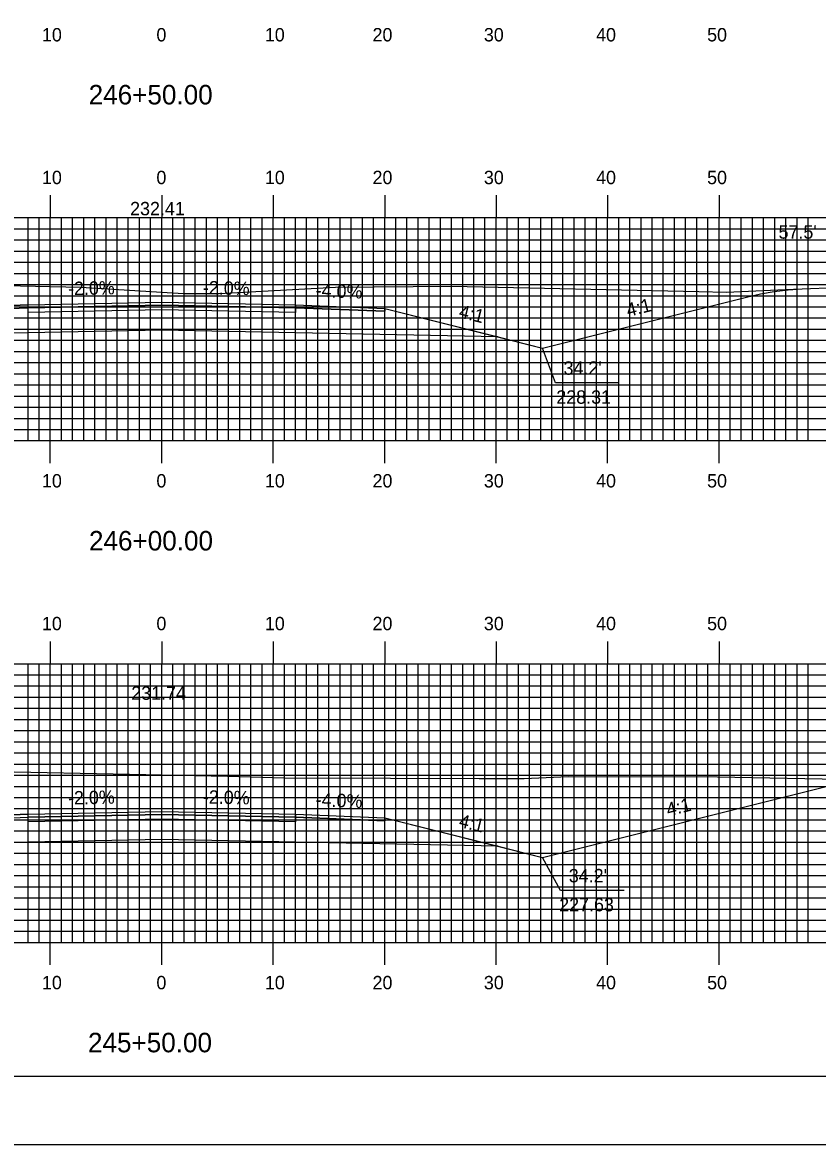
# Model space of a CAD drawing. Extents: x 1803110 to 1803453, y 442591 to 442811.
# Drawn here: x 1803263.1 to 1803334.5, y 442590.5 to 442691.2 of the extents above; entities that cross this region are included whole.
import ezdxf

# ---------------------------------------------------------------- set-up
doc = ezdxf.new("R2010")
doc.units = 0
for name, color, linetype in [('ANNOTATION', 7, 'Continuous'), ('BORDER', 7, 'Continuous'), ('D_Roadway_Centerline', 7, 'Continuous'), ('D_Roadway_Centerline_Text', 7, 'Continuous'), ('D_Roadway_Edge_Shoulder', 7, 'Continuous'), ('D_Roadway_Edge_TW', 7, 'Continuous'), ('D_Roadway_Pavement', 7, 'Continuous'), ('D_Roadway_SlopeLines', 7, 'Continuous'), ('D_Roadway_SubGrade', 7, 'Continuous'), ('D_Text_Standard', 7, 'Continuous'), ('H_V ANNOTATION', 7, 'Continuous'), ('MAJOR', 7, 'Continuous'), ('MINOR', 7, 'Continuous'), ('PLOT BOUNDARY', 7, 'Continuous'), ('S_Roadway_Centerline', 7, 'Continuous')]:
    doc.layers.add(name, color=color, linetype=linetype)

msp = doc.modelspace()

# ---------------------------------------------------------------- linework, layer by layer
at = {"layer": 'ANNOTATION'}
for points in [[(1803316.64, 442658.85), (1803310.95, 442658.85), (1803309.8, 442661.97)], [(1803317.11, 442613.34), (1803311.42, 442613.34), (1803309.8, 442616.3)]]:
    msp.add_lwpolyline(points, dxfattribs=at)
at = {"layer": 'BORDER'}
msp.add_lwpolyline([(1803126.03, 442596.67), (1803446.03, 442596.67), (1803446.03, 442806.67), (1803126.03, 442806.67)], close=True, dxfattribs=at)
at = {"layer": 'D_Roadway_Centerline'}
for points in [[(1803216.26, 442667.67), (1803217.51, 442667.62), (1803218.76, 442667.5), (1803220.01, 442667.3), (1803221.26, 442667.02), (1803241.45, 442661.97), (1803245.45, 442662.97), (1803255.63, 442665.52), (1803263.63, 442665.84), (1803275.63, 442666.08), (1803287.63, 442665.84), (1803295.63, 442665.52), (1803305.8, 442662.97), (1803309.8, 442661.97), (1803328.09, 442666.55), (1803329.34, 442666.83), (1803330.59, 442667.04), (1803331.84, 442667.19), (1803333.09, 442667.27)], [(1803208.67, 442623.85), (1803209.92, 442623.82), (1803211.17, 442623.71), (1803212.42, 442623.52), (1803213.67, 442623.24), (1803241.45, 442616.3), (1803245.45, 442617.3), (1803255.63, 442619.84), (1803263.63, 442620.16), (1803275.63, 442620.4), (1803287.63, 442620.16), (1803295.63, 442619.84), (1803305.8, 442617.3), (1803309.8, 442616.3), (1803335.24, 442622.66), (1803336.49, 442622.93), (1803337.74, 442623.13), (1803338.99, 442623.24), (1803340.24, 442623.28)]]:
    msp.add_lwpolyline(points, dxfattribs=at)
at = {"layer": 'D_Roadway_Edge_Shoulder'}
for points in [[(1803263.63, 442665.84), (1803255.63, 442665.52), (1803255.63, 442665.27), (1803263.63, 442665.59)], [(1803287.63, 442665.84), (1803295.63, 442665.52), (1803295.63, 442665.27), (1803287.63, 442665.59)], [(1803263.63, 442620.16), (1803255.63, 442619.84), (1803255.63, 442619.59), (1803263.63, 442619.91)], [(1803287.63, 442620.16), (1803295.63, 442619.84), (1803295.63, 442619.59), (1803287.63, 442619.91)]]:
    msp.add_lwpolyline(points, close=True, dxfattribs=at)
at = {"layer": 'D_Roadway_Edge_TW'}
for points in [[(1803263.63, 442665.59), (1803263.63, 442665.84), (1803275.63, 442666.08), (1803287.63, 442665.84), (1803287.63, 442665.59), (1803275.63, 442665.83)], [(1803263.63, 442619.91), (1803263.63, 442620.16), (1803275.63, 442620.4), (1803287.63, 442620.16), (1803287.63, 442619.91), (1803275.63, 442620.15)]]:
    msp.add_lwpolyline(points, close=True, dxfattribs=at)
at = {"layer": 'D_Roadway_Pavement'}
for points in [[(1803263.63, 442665.17), (1803263.63, 442665.59), (1803275.63, 442665.83), (1803287.63, 442665.59), (1803287.63, 442665.17), (1803275.63, 442665.41)], [(1803263.63, 442619.49), (1803263.63, 442619.91), (1803275.63, 442620.15), (1803287.63, 442619.91), (1803287.63, 442619.49), (1803275.63, 442619.73)]]:
    msp.add_lwpolyline(points, close=True, dxfattribs=at)
at = {"layer": 'D_Roadway_SlopeLines'}
for points in [[(1803309.8, 442661.97), (1803328.09, 442666.55), (1803329.34, 442666.83), (1803330.59, 442667.04), (1803331.84, 442667.19), (1803333.09, 442667.27)], [(1803295.63, 442665.52), (1803309.8, 442661.97)], [(1803309.8, 442616.3), (1803335.24, 442622.66), (1803336.49, 442622.93), (1803337.74, 442623.13), (1803338.99, 442623.24), (1803340.24, 442623.28)], [(1803295.63, 442619.84), (1803309.8, 442616.3)]]:
    msp.add_lwpolyline(points, dxfattribs=at)
at = {"layer": 'D_Roadway_SubGrade'}
for points in [[(1803263.63, 442663.34), (1803245.45, 442662.97), (1803255.63, 442665.52), (1803255.63, 442665.27), (1803263.63, 442665.59), (1803275.63, 442665.83), (1803287.63, 442665.59), (1803295.63, 442665.27), (1803295.63, 442665.52), (1803305.8, 442662.97), (1803287.63, 442663.34), (1803275.63, 442663.58)], [(1803263.63, 442617.66), (1803245.45, 442617.3), (1803255.63, 442619.84), (1803255.63, 442619.59), (1803263.63, 442619.91), (1803275.63, 442620.15), (1803287.63, 442619.91), (1803295.63, 442619.59), (1803295.63, 442619.84), (1803305.8, 442617.3), (1803287.63, 442617.66), (1803275.63, 442617.9)]]:
    msp.add_lwpolyline(points, close=True, dxfattribs=at)
at = {"layer": 'MAJOR'}
for p, q in [((1803265.63, 442675.67), (1803265.63, 442673.67)), ((1803275.63, 442675.67), (1803275.63, 442673.67)), ((1803285.63, 442675.67), (1803285.63, 442673.67)), ((1803295.63, 442675.67), (1803295.63, 442673.67)), ((1803305.63, 442675.67), (1803305.63, 442673.67)), ((1803315.63, 442675.67), (1803315.63, 442673.67)), ((1803325.63, 442675.67), (1803325.63, 442673.67)), ((1803135.63, 442673.67), (1803415.63, 442673.67)), ((1803135.63, 442673.67), (1803415.63, 442673.67)), ((1803265.63, 442653.67), (1803265.63, 442673.67)), ((1803275.63, 442653.67), (1803275.63, 442673.67)), ((1803285.63, 442653.67), (1803285.63, 442673.67)), ((1803295.63, 442653.67), (1803295.63, 442673.67)), ((1803305.63, 442653.67), (1803305.63, 442673.67)), ((1803315.63, 442653.67), (1803315.63, 442673.67)), ((1803325.63, 442653.67), (1803325.63, 442673.67)), ((1803135.63, 442668.67), (1803415.63, 442668.67)), ((1803135.63, 442663.67), (1803415.63, 442663.67)), ((1803135.63, 442658.67), (1803415.63, 442658.67)), ((1803135.63, 442653.67), (1803415.63, 442653.67)), ((1803135.63, 442653.67), (1803415.63, 442653.67)), ((1803265.63, 442651.66), (1803265.63, 442653.67)), ((1803275.63, 442651.66), (1803275.63, 442653.67)), ((1803285.63, 442651.66), (1803285.63, 442653.67)), ((1803295.63, 442651.66), (1803295.63, 442653.67)), ((1803305.63, 442651.66), (1803305.63, 442653.67)), ((1803315.63, 442651.66), (1803315.63, 442653.67)), ((1803325.63, 442651.66), (1803325.63, 442653.67)), ((1803265.63, 442635.67), (1803265.63, 442633.67)), ((1803275.63, 442635.67), (1803275.63, 442633.67)), ((1803285.63, 442635.67), (1803285.63, 442633.67)), ((1803295.63, 442635.67), (1803295.63, 442633.67)), ((1803305.63, 442635.67), (1803305.63, 442633.67)), ((1803315.63, 442635.67), (1803315.63, 442633.67)), ((1803325.63, 442635.67), (1803325.63, 442633.67)), ((1803135.63, 442633.67), (1803415.63, 442633.67)), ((1803135.63, 442633.67), (1803415.63, 442633.67)), ((1803265.63, 442608.67), (1803265.63, 442633.67)), ((1803275.63, 442608.67), (1803275.63, 442633.67)), ((1803285.63, 442608.67), (1803285.63, 442633.67)), ((1803295.63, 442608.67), (1803295.63, 442633.67)), ((1803305.63, 442608.67), (1803305.63, 442633.67)), ((1803315.63, 442608.67), (1803315.63, 442633.67)), ((1803325.63, 442608.67), (1803325.63, 442633.67)), ((1803135.63, 442628.67), (1803415.63, 442628.67)), ((1803135.63, 442623.67), (1803415.63, 442623.67)), ((1803135.63, 442618.67), (1803415.63, 442618.67)), ((1803135.63, 442613.67), (1803415.63, 442613.67)), ((1803135.63, 442608.67), (1803415.63, 442608.67)), ((1803135.63, 442608.67), (1803415.63, 442608.67)), ((1803265.63, 442606.66), (1803265.63, 442608.67)), ((1803275.63, 442606.66), (1803275.63, 442608.67)), ((1803285.63, 442606.66), (1803285.63, 442608.67)), ((1803295.63, 442606.66), (1803295.63, 442608.67)), ((1803305.63, 442606.66), (1803305.63, 442608.67)), ((1803315.63, 442606.66), (1803315.63, 442608.67)), ((1803325.63, 442606.66), (1803325.63, 442608.67))]:
    msp.add_line(p, q, dxfattribs=at)
at = {"layer": 'MINOR'}
for p, q in [((1803263.63, 442653.67), (1803263.63, 442673.67)), ((1803264.63, 442653.67), (1803264.63, 442673.67)), ((1803266.63, 442653.67), (1803266.63, 442673.67)), ((1803267.63, 442653.67), (1803267.63, 442673.67)), ((1803268.63, 442653.67), (1803268.63, 442673.67)), ((1803269.63, 442653.67), (1803269.63, 442673.67)), ((1803270.63, 442653.67), (1803270.63, 442673.67)), ((1803271.63, 442653.67), (1803271.63, 442673.67)), ((1803272.63, 442653.67), (1803272.63, 442673.67)), ((1803273.63, 442653.67), (1803273.63, 442673.67)), ((1803274.63, 442653.67), (1803274.63, 442673.67)), ((1803276.63, 442653.67), (1803276.63, 442673.67)), ((1803277.63, 442653.67), (1803277.63, 442673.67)), ((1803278.63, 442653.67), (1803278.63, 442673.67)), ((1803279.63, 442653.67), (1803279.63, 442673.67)), ((1803280.63, 442653.67), (1803280.63, 442673.67)), ((1803281.63, 442653.67), (1803281.63, 442673.67)), ((1803282.63, 442653.67), (1803282.63, 442673.67)), ((1803283.63, 442653.67), (1803283.63, 442673.67)), ((1803284.63, 442653.67), (1803284.63, 442673.67)), ((1803286.63, 442653.67), (1803286.63, 442673.67)), ((1803287.63, 442653.67), (1803287.63, 442673.67)), ((1803288.63, 442653.67), (1803288.63, 442673.67)), ((1803289.63, 442653.67), (1803289.63, 442673.67)), ((1803290.63, 442653.67), (1803290.63, 442673.67)), ((1803291.63, 442653.67), (1803291.63, 442673.67)), ((1803292.63, 442653.67), (1803292.63, 442673.67)), ((1803293.63, 442653.67), (1803293.63, 442673.67)), ((1803294.63, 442653.67), (1803294.63, 442673.67)), ((1803296.63, 442653.67), (1803296.63, 442673.67)), ((1803297.63, 442653.67), (1803297.63, 442673.67)), ((1803298.63, 442653.67), (1803298.63, 442673.67)), ((1803299.63, 442653.67), (1803299.63, 442673.67)), ((1803300.63, 442653.67), (1803300.63, 442673.67)), ((1803301.63, 442653.67), (1803301.63, 442673.67)), ((1803302.63, 442653.67), (1803302.63, 442673.67)), ((1803303.63, 442653.67), (1803303.63, 442673.67)), ((1803304.63, 442653.67), (1803304.63, 442673.67)), ((1803306.63, 442653.67), (1803306.63, 442673.67)), ((1803307.63, 442653.67), (1803307.63, 442673.67)), ((1803308.63, 442653.67), (1803308.63, 442673.67)), ((1803309.63, 442653.67), (1803309.63, 442673.67)), ((1803310.63, 442653.67), (1803310.63, 442673.67)), ((1803311.63, 442653.67), (1803311.63, 442673.67)), ((1803312.63, 442653.67), (1803312.63, 442673.67)), ((1803313.63, 442653.67), (1803313.63, 442673.67)), ((1803314.63, 442653.67), (1803314.63, 442673.67)), ((1803316.63, 442653.67), (1803316.63, 442673.67)), ((1803317.63, 442653.67), (1803317.63, 442673.67)), ((1803318.63, 442653.67), (1803318.63, 442673.67)), ((1803319.63, 442653.67), (1803319.63, 442673.67)), ((1803320.63, 442653.67), (1803320.63, 442673.67)), ((1803321.63, 442653.67), (1803321.63, 442673.67)), ((1803322.63, 442653.67), (1803322.63, 442673.67)), ((1803323.63, 442653.67), (1803323.63, 442673.67)), ((1803324.63, 442653.67), (1803324.63, 442673.67)), ((1803326.63, 442653.67), (1803326.63, 442673.67)), ((1803327.63, 442653.67), (1803327.63, 442673.67)), ((1803328.63, 442653.67), (1803328.63, 442673.67)), ((1803329.63, 442653.67), (1803329.63, 442673.67)), ((1803330.63, 442653.67), (1803330.63, 442673.67)), ((1803331.63, 442653.67), (1803331.63, 442673.67)), ((1803332.63, 442653.67), (1803332.63, 442673.67)), ((1803333.63, 442653.67), (1803333.63, 442673.67)), ((1803135.63, 442672.67), (1803415.63, 442672.67)), ((1803135.63, 442671.67), (1803415.63, 442671.67)), ((1803135.63, 442670.67), (1803415.63, 442670.67)), ((1803135.63, 442669.67), (1803415.63, 442669.67)), ((1803135.63, 442667.67), (1803415.63, 442667.67)), ((1803135.63, 442666.67), (1803415.63, 442666.67)), ((1803135.63, 442665.67), (1803415.63, 442665.67)), ((1803135.63, 442664.67), (1803415.63, 442664.67)), ((1803135.63, 442662.67), (1803415.63, 442662.67)), ((1803135.63, 442661.67), (1803415.63, 442661.67)), ((1803135.63, 442660.67), (1803415.63, 442660.67)), ((1803135.63, 442659.67), (1803415.63, 442659.67)), ((1803135.63, 442657.67), (1803415.63, 442657.67)), ((1803135.63, 442656.67), (1803415.63, 442656.67)), ((1803135.63, 442655.67), (1803415.63, 442655.67)), ((1803135.63, 442654.67), (1803415.63, 442654.67)), ((1803263.63, 442608.67), (1803263.63, 442633.67)), ((1803264.63, 442608.67), (1803264.63, 442633.67)), ((1803266.63, 442608.67), (1803266.63, 442633.67)), ((1803267.63, 442608.67), (1803267.63, 442633.67)), ((1803268.63, 442608.67), (1803268.63, 442633.67)), ((1803269.63, 442608.67), (1803269.63, 442633.67)), ((1803270.63, 442608.67), (1803270.63, 442633.67)), ((1803271.63, 442608.67), (1803271.63, 442633.67)), ((1803272.63, 442608.67), (1803272.63, 442633.67)), ((1803273.63, 442608.67), (1803273.63, 442633.67)), ((1803274.63, 442608.67), (1803274.63, 442633.67)), ((1803276.63, 442608.67), (1803276.63, 442633.67)), ((1803277.63, 442608.67), (1803277.63, 442633.67)), ((1803278.63, 442608.67), (1803278.63, 442633.67)), ((1803279.63, 442608.67), (1803279.63, 442633.67)), ((1803280.63, 442608.67), (1803280.63, 442633.67)), ((1803281.63, 442608.67), (1803281.63, 442633.67)), ((1803282.63, 442608.67), (1803282.63, 442633.67)), ((1803283.63, 442608.67), (1803283.63, 442633.67)), ((1803284.63, 442608.67), (1803284.63, 442633.67)), ((1803286.63, 442608.67), (1803286.63, 442633.67)), ((1803287.63, 442608.67), (1803287.63, 442633.67)), ((1803288.63, 442608.67), (1803288.63, 442633.67)), ((1803289.63, 442608.67), (1803289.63, 442633.67)), ((1803290.63, 442608.67), (1803290.63, 442633.67)), ((1803291.63, 442608.67), (1803291.63, 442633.67)), ((1803292.63, 442608.67), (1803292.63, 442633.67)), ((1803293.63, 442608.67), (1803293.63, 442633.67)), ((1803294.63, 442608.67), (1803294.63, 442633.67)), ((1803296.63, 442608.67), (1803296.63, 442633.67)), ((1803297.63, 442608.67), (1803297.63, 442633.67)), ((1803298.63, 442608.67), (1803298.63, 442633.67)), ((1803299.63, 442608.67), (1803299.63, 442633.67)), ((1803300.63, 442608.67), (1803300.63, 442633.67)), ((1803301.63, 442608.67), (1803301.63, 442633.67)), ((1803302.63, 442608.67), (1803302.63, 442633.67)), ((1803303.63, 442608.67), (1803303.63, 442633.67)), ((1803304.63, 442608.67), (1803304.63, 442633.67)), ((1803306.63, 442608.67), (1803306.63, 442633.67)), ((1803307.63, 442608.67), (1803307.63, 442633.67)), ((1803308.63, 442608.67), (1803308.63, 442633.67)), ((1803309.63, 442608.67), (1803309.63, 442633.67)), ((1803310.63, 442608.67), (1803310.63, 442633.67)), ((1803311.63, 442608.67), (1803311.63, 442633.67)), ((1803312.63, 442608.67), (1803312.63, 442633.67)), ((1803313.63, 442608.67), (1803313.63, 442633.67)), ((1803314.63, 442608.67), (1803314.63, 442633.67)), ((1803316.63, 442608.67), (1803316.63, 442633.67)), ((1803317.63, 442608.67), (1803317.63, 442633.67)), ((1803318.63, 442608.67), (1803318.63, 442633.67)), ((1803319.63, 442608.67), (1803319.63, 442633.67)), ((1803320.63, 442608.67), (1803320.63, 442633.67)), ((1803321.63, 442608.67), (1803321.63, 442633.67)), ((1803322.63, 442608.67), (1803322.63, 442633.67)), ((1803323.63, 442608.67), (1803323.63, 442633.67)), ((1803324.63, 442608.67), (1803324.63, 442633.67)), ((1803326.63, 442608.67), (1803326.63, 442633.67)), ((1803327.63, 442608.67), (1803327.63, 442633.67)), ((1803328.63, 442608.67), (1803328.63, 442633.67)), ((1803329.63, 442608.67), (1803329.63, 442633.67)), ((1803330.63, 442608.67), (1803330.63, 442633.67)), ((1803331.63, 442608.67), (1803331.63, 442633.67)), ((1803332.63, 442608.67), (1803332.63, 442633.67)), ((1803333.63, 442608.67), (1803333.63, 442633.67)), ((1803135.63, 442632.67), (1803415.63, 442632.67)), ((1803135.63, 442631.67), (1803415.63, 442631.67)), ((1803135.63, 442630.67), (1803415.63, 442630.67)), ((1803135.63, 442629.67), (1803415.63, 442629.67)), ((1803135.63, 442627.67), (1803415.63, 442627.67)), ((1803135.63, 442626.67), (1803415.63, 442626.67)), ((1803135.63, 442625.67), (1803415.63, 442625.67)), ((1803135.63, 442624.67), (1803415.63, 442624.67)), ((1803135.63, 442622.67), (1803415.63, 442622.67)), ((1803135.63, 442621.67), (1803415.63, 442621.67)), ((1803135.63, 442620.67), (1803415.63, 442620.67)), ((1803135.63, 442619.67), (1803415.63, 442619.67)), ((1803135.63, 442617.67), (1803415.63, 442617.67)), ((1803135.63, 442616.67), (1803415.63, 442616.67)), ((1803135.63, 442615.67), (1803415.63, 442615.67)), ((1803135.63, 442614.67), (1803415.63, 442614.67)), ((1803135.63, 442612.67), (1803415.63, 442612.67)), ((1803135.63, 442611.67), (1803415.63, 442611.67)), ((1803135.63, 442610.67), (1803415.63, 442610.67)), ((1803135.63, 442609.67), (1803415.63, 442609.67))]:
    msp.add_line(p, q, dxfattribs=at)
at = {"layer": 'PLOT BOUNDARY'}
msp.add_lwpolyline([(1803109.84, 442590.55), (1803449.84, 442590.55), (1803449.84, 442810.55), (1803109.84, 442810.55)], close=True, dxfattribs=at)
at = {"layer": 'S_Roadway_Centerline'}
for points in [[(1803200.7, 442667.63), (1803217.19, 442667.67), (1803220.81, 442667.62), (1803225.55, 442667.56), (1803233.02, 442667.5), (1803238.55, 442667.5), (1803251.74, 442667.64), (1803255.42, 442667.71), (1803258.86, 442667.64), (1803268.38, 442667.44), (1803277.59, 442666.86), (1803280.77, 442666.87), (1803291.21, 442667.42), (1803301.67, 442667.52), (1803323.83, 442667.05), (1803326.31, 442666.97), (1803329.6, 442667.13), (1803331.57, 442667.21), (1803337.63, 442667.46)], [(1803203.03, 442623.87), (1803209.31, 442623.84), (1803218.86, 442623.97), (1803234.63, 442623.63), (1803239.72, 442623.61), (1803260.41, 442624.01), (1803260.67, 442624), (1803260.89, 442624), (1803272.73, 442623.75), (1803281.53, 442623.59), (1803286.63, 442623.44), (1803296.14, 442623.39), (1803304.1, 442623.38), (1803308.16, 442623.38), (1803312.1, 442623.56), (1803325.5, 442623.51), (1803338.02, 442623.28)]]:
    msp.add_lwpolyline(points, dxfattribs=at)

# ---------------------------------------------------------------- texts
at = {"layer": 'ANNOTATION'}
for s, rotation, p in [('-2.0%', 1.1458, (1803267.23, 442666.71)), ('-2.0%', 358.8542, (1803279.31, 442666.8)), ('-4.0%', 357.7094, (1803289.42, 442666.57)), ('4:1', 345.9638, (1803302.22, 442664.73)), ('4:1', 14.0362, (1803317.48, 442664.76)), ('-2.0%', 1.1458, (1803267.23, 442621.03)), ('-2.0%', 358.8542, (1803279.31, 442621.13)), ('-4.0%', 357.7094, (1803289.42, 442620.89)), ('4:1', 14.0362, (1803321.06, 442619.97)), ('4:1', 345.9638, (1803302.22, 442619.05))]:
    msp.add_text(s, height=1.2, rotation=rotation, dxfattribs=at).set_placement(p)
for s, p in [("34.2'", (1803311.68, 442659.58)), ('228.31', (1803311.03, 442656.98)), ("34.2'", (1803312.15, 442614.06)), ('227.63', (1803311.29, 442611.46))]:
    msp.add_text(s, height=1.2, dxfattribs=at).set_placement(p)
at = {"layer": 'D_Roadway_Centerline'}
for s, p in [('C', (1803275.62, 442666.08)), ('L', (1803275.63, 442666.07)), ('C', (1803275.62, 442620.4)), ('L', (1803275.63, 442620.39))]:
    msp.add_text(s, height=0.0146, dxfattribs=at).set_placement(p)
at = {"layer": 'D_Roadway_Centerline_Text'}
for s, p in [('232.41', (1803272.79, 442673.88)), ('231.74', (1803272.89, 442630.43))]:
    msp.add_text(s, height=1.2, dxfattribs=at).set_placement(p)
at = {"layer": 'D_Text_Standard'}
msp.add_text("57.5'", height=1.2, dxfattribs=at).set_placement((1803330.97, 442671.78))
at = {"layer": 'H_V ANNOTATION'}
for s, height, p in [('10', 1.2, (1803264.88, 442689.47)), ('0', 1.2, (1803275.15, 442689.47)), ('10', 1.2, (1803284.88, 442689.47)), ('20', 1.2, (1803294.54, 442689.47)), ('30', 1.2, (1803304.53, 442689.47)), ('40', 1.2, (1803314.6, 442689.47)), ('50', 1.2, (1803324.56, 442689.47)), ('246+50.00', 1.75, (1803269.07, 442683.82)), ('10', 1.2, (1803264.88, 442676.67)), ('0', 1.2, (1803275.15, 442676.67)), ('10', 1.2, (1803284.88, 442676.67)), ('20', 1.2, (1803294.54, 442676.67)), ('30', 1.2, (1803304.53, 442676.67)), ('40', 1.2, (1803314.6, 442676.67)), ('50', 1.2, (1803324.56, 442676.67)), ('10', 1.2, (1803264.88, 442649.47)), ('0', 1.2, (1803275.15, 442649.47)), ('10', 1.2, (1803284.88, 442649.47)), ('20', 1.2, (1803294.54, 442649.47)), ('30', 1.2, (1803304.53, 442649.47)), ('40', 1.2, (1803314.6, 442649.47)), ('50', 1.2, (1803324.56, 442649.47)), ('246+00.00', 1.75, (1803269.1, 442643.82)), ('10', 1.2, (1803264.88, 442636.67)), ('0', 1.2, (1803275.15, 442636.67)), ('10', 1.2, (1803284.88, 442636.67)), ('20', 1.2, (1803294.54, 442636.67)), ('30', 1.2, (1803304.53, 442636.67)), ('40', 1.2, (1803314.6, 442636.67)), ('50', 1.2, (1803324.56, 442636.67)), ('10', 1.2, (1803264.88, 442604.47)), ('0', 1.2, (1803275.15, 442604.47)), ('10', 1.2, (1803284.88, 442604.47)), ('20', 1.2, (1803294.54, 442604.47)), ('30', 1.2, (1803304.53, 442604.47)), ('40', 1.2, (1803314.6, 442604.47)), ('50', 1.2, (1803324.56, 442604.47)), ('245+50.00', 1.75, (1803269.01, 442598.82))]:
    msp.add_text(s, height=height, dxfattribs=at).set_placement(p)

doc.saveas('drawing.dxf')
